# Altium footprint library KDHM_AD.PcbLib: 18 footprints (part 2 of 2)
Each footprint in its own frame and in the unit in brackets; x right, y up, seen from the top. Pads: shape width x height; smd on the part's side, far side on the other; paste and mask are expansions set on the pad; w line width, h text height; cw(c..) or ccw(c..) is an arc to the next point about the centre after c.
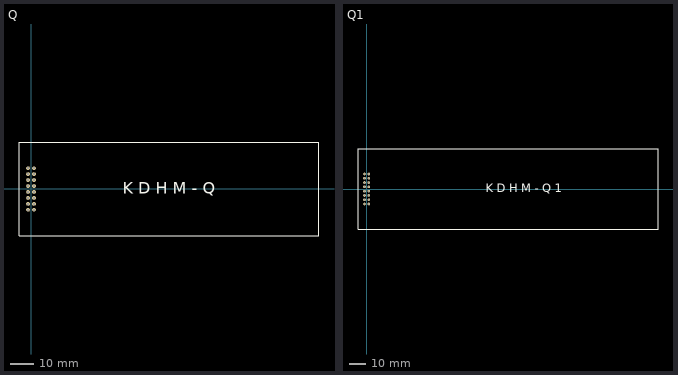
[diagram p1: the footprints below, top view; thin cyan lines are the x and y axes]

## Q [mm]
pads (16):
  round 1.6 hole 0.8: +Vin(-1.27,-6.35) +Vin(1.27,-6.35) GND(-1.27,-8.89) GND(-1.27,1.27) GND(-1.27,6.35) GND(1.27,-8.89) GND(1.27,1.27) GND(1.27,6.35) IAdj(1.27,-1.27) Im(1.27,3.81) MLED(-1.27,8.89) Sleep(1.27,8.89) VAdj(-1.27,-1.27) Vm(-1.27,3.81) Vref(-1.27,-3.81) Vref(1.27,-3.81)
TopOverlay:
  lines w0.2: -5.13,-20 -5.13,20 122.87,20 122.87,-20 -5.13,-20
  text "K D H M - Q" at 39.116,-2.032 h5

## Q1 [mm]
pads (16):
  round 1.6 hole 0.8: +Vin(-1.27,-6.35) +Vin(1.27,-6.35) GND(-1.27,-8.89) GND(-1.27,1.27) GND(-1.27,6.35) GND(1.27,-8.89) GND(1.27,1.27) GND(1.27,6.35) IAdj(1.27,-1.27) Im(1.27,3.81) MLED(-1.27,8.89) Sleep(1.27,8.89) VAdj(-1.27,-1.27) Vm(-1.27,3.81) Vref(-1.27,-3.81) Vref(1.27,-3.81)
TopOverlay:
  lines w0.2: -5.13,-24 172.87,-24 172.87,24 -5.13,24 -5.13,-24
  text "K D H M - Q 1" at 70.612,-2.032 h5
